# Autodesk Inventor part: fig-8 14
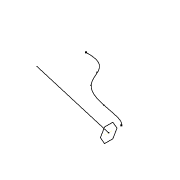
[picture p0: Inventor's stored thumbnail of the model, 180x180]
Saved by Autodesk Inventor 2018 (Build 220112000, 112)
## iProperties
Created: 2004-05
Part Number: fig-8 14
Document SubType Name: Modeling
Designer: CADCIM Technologies
Manufacturer: Standard
Standards Organization: Custom
Density: 1 g/cm^3
Material: Generic
Appearance: Default
Author: CADCIM Technologies
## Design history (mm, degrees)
workplane "Work Plane2"
sketch "Sketch7"
  geometry: L1 (-42.583, 6.068)-(-42.583, 0.37) reference; 5 further points
  constraints: 1 point on line, 5 other
sketch "Sketch8"
  geometry: L1 (-42.583, 3.219)-(-107.269, 18.236); L2 (-42.583, 6.068)-(-42.583, 0.37) reference
  constraints: 2 end point, 1 midpoint
sketch "Sketch2"
  geometry: L1 (-5.697, 0)-(-2.849, 4.934); L2 (-2.849, 4.934)-(2.849, 4.934); L3 (2.849, 4.934)-(5.697, 0); L4 (5.697, 0)-(2.849, -4.934); L5 (2.849, -4.934)-(-2.849, -4.934); L6 (-2.849, -4.934)-(-5.697, 0); 2 further points
  constraints: 12 end point, 1 coincident, 12 other
